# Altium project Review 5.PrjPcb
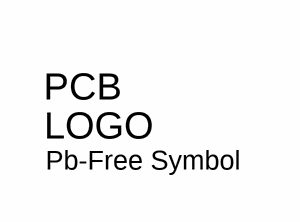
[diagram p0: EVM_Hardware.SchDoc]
CopyrightYear: 2017; PCB_Layout: Ismael Nunez; PCB_Rev: E1; PRJ_Customer: Sunon; PRJ_Engineer: Sunon Server Fan; PRJ_Number: TIDA-01619; PRJ_Title: Sunon Server Fan; SCH_Rev: E1; TechSupport: http://www.ti.com/support; TID: TIDA-01619
2 sheets, 18 parts. Net scope: flat (ports and power ports of the same name join across sheets).
Board file: Sunon PCB.PcbDoc
Sheets:
  EVM_Hardware.SchDoc
  Sunon Layout.SchDoc

## Sheet EVM_Hardware.SchDoc
size 431 x 279 mm; Date: Not shown in title block; ApprovedBy: Not shown in title block; CheckedBy: Not shown in title block; Author: Not shown in title block; CompanyName: Not shown in title block; Engineer: Not shown in title block; Organization: Not shown in title block; Address1: Not shown in title block; Address2: Not shown in title block; Address3: Not shown in title block; Address4: Not shown in title block; DocumentNumber: 1; Revision: Use project parameter SCH_Rev; SheetNumber: 3; SheetTotal: 3; PageSetup: Record=PageOptions¦CenterHorizontal=True¦CenterVertical=True¦PrintScale=1.00¦XCorrection=1.00¦YCorrection=1.00¦PrintKind=0¦BorderSize=5000000¦LeftOffset=0¦BottomOffset=0¦Orientation=2¦PaperLength=1000¦PaperWidth=1000¦Scale=100¦PaperSource=15¦PrintQuality=600¦MediaType=1¦DitherType=10¦PaperKind=Letter¦PrintScaleMode=1

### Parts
Logo2  Pb-Free Symbol  [Pb-Free_Overlay_Small]  (no BOM)

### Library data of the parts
Logo2 = CMP-0074839-1: SymbolCreator: a0412235; Library Reference: Logo

## Sheet Sunon Layout.SchDoc
size 431 x 279 mm; Date: Not shown in title block; ApprovedBy: Not shown in title block; CheckedBy: Not shown in title block; Author: Not shown in title block; CompanyName: Not shown in title block; Engineer: Not shown in title block; Organization: Not shown in title block; Address1: Not shown in title block; Address2: Not shown in title block; Address3: Not shown in title block; Address4: Not shown in title block; DocumentNumber: 1; Revision: Use project parameter SCH_Rev; SheetNumber: 2; SheetTotal: 3; PageSetup: Record=PageOptions¦CenterHorizontal=True¦CenterVertical=True¦PrintScale=1.00¦XCorrection=1.00¦YCorrection=1.00¦PrintKind=0¦BorderSize=5000000¦LeftOffset=0¦BottomOffset=0¦Orientation=2¦PaperLength=1000¦PaperWidth=1000¦Scale=100¦PaperSource=15¦PrintQuality=600¦MediaType=1¦DitherType=10¦PaperKind=Letter¦PrintScaleMode=1
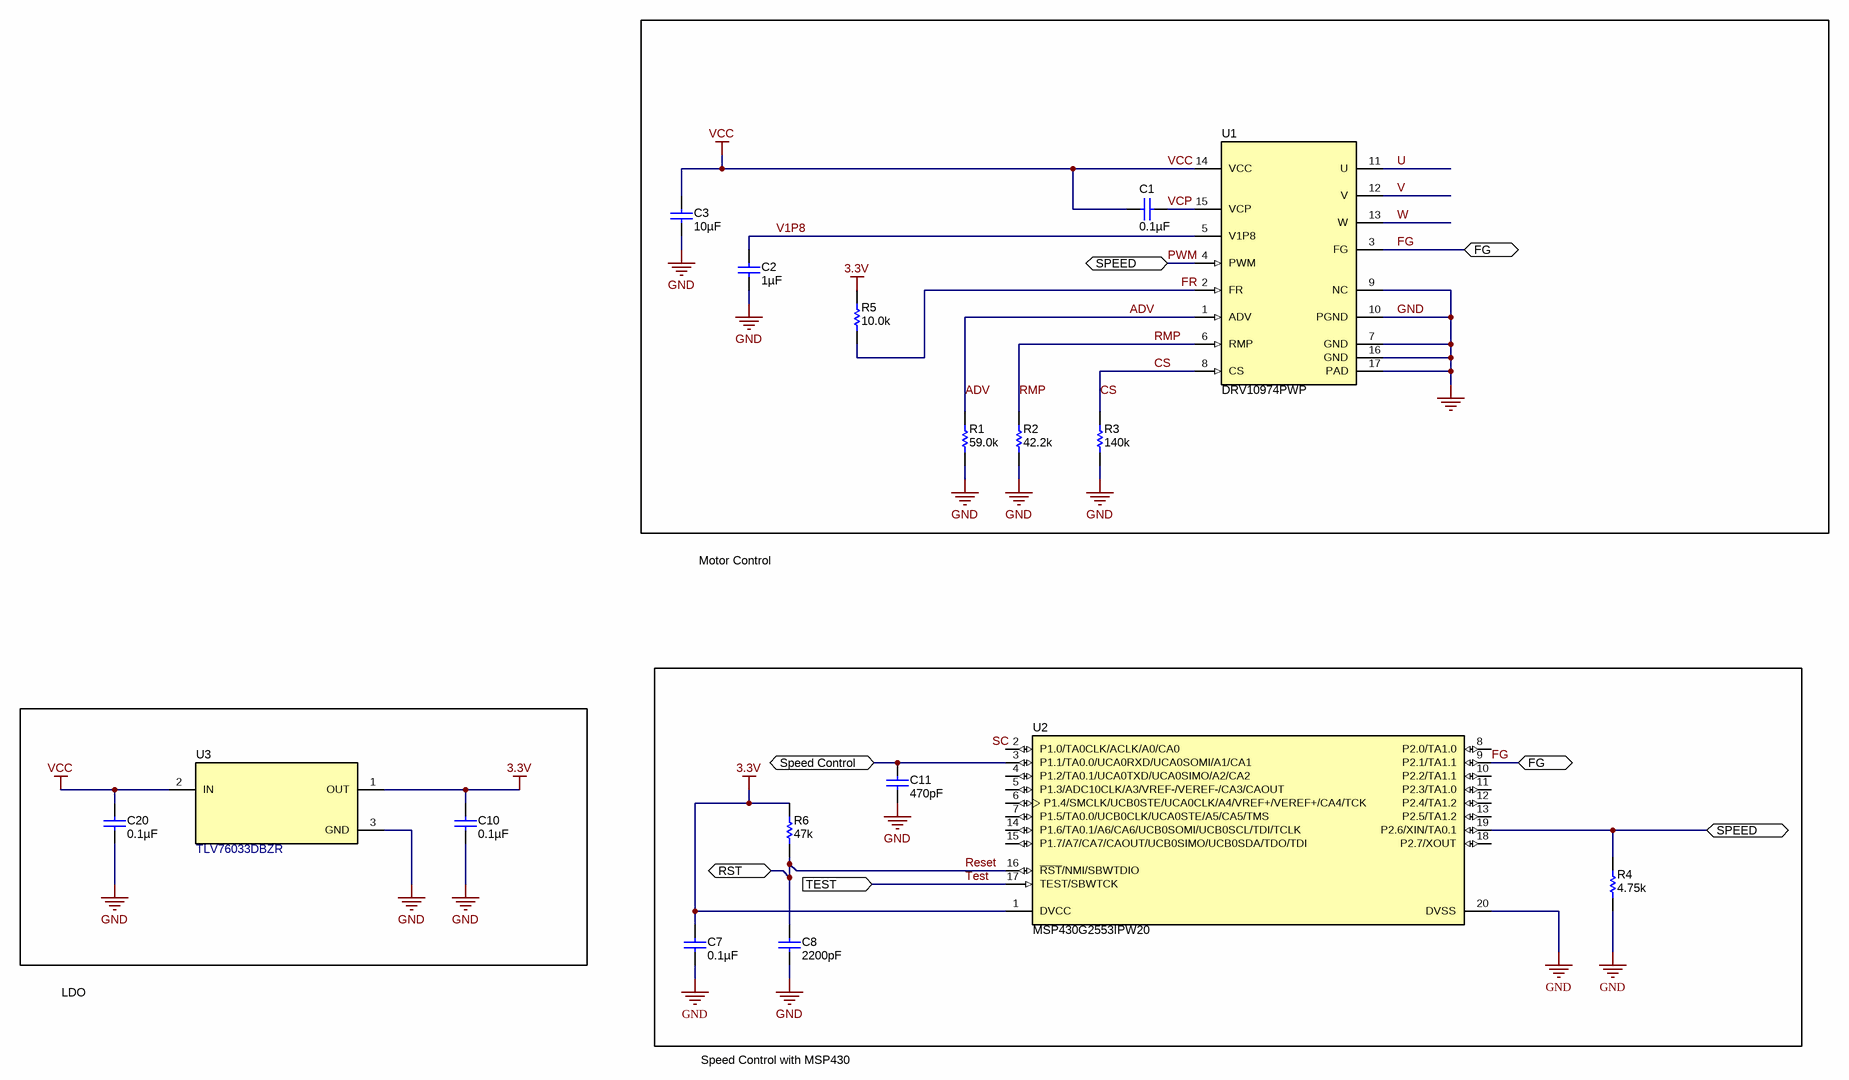
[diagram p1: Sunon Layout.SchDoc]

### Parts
C1  ValueDisplayed: 0.1µF  [0402]  (hidden comment: C1005X5R1H104K050BB)
C2  ValueDisplayed: 1µF  [0402_070]  (hidden comment: GCM155C71A105KE38D)
C3  ValueDisplayed: 10µF  [0603]  (hidden comment: GRM188R61C106MAALD)
C7  ValueDisplayed: 0.1µF  [0402]  (hidden comment: C1005X5R1H104K050BB)
C8  ValueDisplayed: 2200pF  [0402]  (hidden comment: CGA2B2X7R1H222K050BA)
C10  ValueDisplayed: 0.1µF  [0402]  (hidden comment: C1005X5R1H104K050BB)
C11  ValueDisplayed: 470pF  [0402]  (hidden comment: CGA2B2X7R1H471K050BA)
C20  ValueDisplayed: 0.1µF  [0402]  (hidden comment: C1005X5R1H104K050BB)
R1  ValueDisplayed: 59.0k  [0402]  (hidden comment: CRCW040259K0FKED)
R2  ValueDisplayed: 42.2k  [0402]  (hidden comment: CRCW040242K2FKED)
R3  ValueDisplayed: 140k  [0402]  (hidden comment: CRCW0402140KFKED)
R4  ValueDisplayed: 4.75k  [0402]  (hidden comment: CRCW04024K75FKED)
R5  ValueDisplayed: 10.0k  [0402]  (hidden comment: CRCW040210K0FKED)
R6  ValueDisplayed: 47k  [0402]  (hidden comment: CRCW040247K0JNED)
U1  DRV10974PWP  [PWP0016J_N]
U2  MSP430G2553IPW20  [PW0020A_N]
U3  TLV76033DBZR  [DBZ0003A_N]

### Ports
FG (bidir), RST (bidir), SPEED (bidir), Speed Control (bidir), TEST (in)

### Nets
3.3V: C7.1 C10.1 R5.1 R6.2 U2.1(DVCC) U3.1(OUT)
GND: C2.2 C3.2 C7.2 C8.2 C10.2 C11.2 C20.2 R1.1 R2.1 R3.1 R4.1 U1.7(GND) U1.9(NC) U1.10(PGND) U1.16(GND) U1.17(PAD) U2.20(DVSS) U3.3(GND)
VCC: C1.1 C3.1 C20.1 U1.14(VCC) U3.2(IN)
ADV: R1.2 U1.1(ADV)
CS: R3.2 U1.8(CS)
FG: U1.3(FG) U2.9(P2.1/TA1.1) ; port FG
FR: R5.2 U1.2(FR)
PWM: R4.2 U1.4(PWM) U2.19(P2.6/XIN/TA0.1) ; port SPEED
Reset: C8.1 R6.1 U2.16(~{RST}/NMI/SBWTDIO) ; port RST
RMP: R2.2 U1.6(RMP)
Speed Control: C11.1 U2.3(P1.1/TA0.0/UCA0RXD/UCA0SOMI/A1/CA1) ; port Speed Control
Test: U2.17(TEST/SBWTCK) ; port TEST
U: U1.11(U)
V: U1.12(V)
V1P8: C2.1 U1.5(V1P8)
VCP: C1.2 U1.15(VCP)
W: U1.13(W)

Not connected (* = marked no-connect by the designer): U2 2(P1.0/TA0CLK/ACLK/A0/CA0) 4(P1.2/TA0.1/UCA0TXD/UCA0SIMO/A2/CA2) 5(P1.3/ADC10CLK/A3/VREF-/VEREF-/CA3/CAOUT) 6(P1.4/SMCLK/UCB0STE/UCA0CLK/A4/VREF+/VEREF+/CA4/TCK) 7(P1.5/TA0.0/UCB0CLK/UCA0STE/A5/CA5/TMS) 8(P2.0/TA1.0) 10(P2.2/TA1.1) 11(P2.3/TA1.0) 12(P2.4/TA1.2) 13(P2.5/TA1.2) 14(P1.6/TA0.1/A6/CA6/UCB0SOMI/UCB0SCL/TDI/TCLK) 15(P1.7/A7/CA7/CAOUT/UCB0SIMO/UCB0SDA/TDO/TDI) 18(P2.7/XOUT)

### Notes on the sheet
- Motor Control
- LDO
- Speed Control with MSP430
- Labels drawn without touching a wire or pin: SC

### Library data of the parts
C1 C7 C10 C20 = C1005X5R1H104K050BB: CAP, CERM, 0.1 µF, 50 V,+/- 10%, X5R, 0402; Manufacturer: TDK; Polarized: N; CompType: Capacitor; Value: 0.1uF; U/M: EA; Cap_F: 0.0000001; Tolerance_%: 10; ESR_ohm: 0.039064; Value1: 0.039064 ohm; VDC_V: 50; Value2: 50V; IRMS_A: 0.814669; TaMin_C: -55; TaMax_C: 85; SizeArea_mm2: 0.5; SizeAreaWB_mm2: 3; SizeX_mm: 1; SizeZ_mm: 0.6; AEC Category: Q200; Green_Lifecycle: NRND; Green_REACh: Passed
C2 = GCM155C71A105KE38D: CAP, CERM, 1 µF, 10 V,+/- 10%, X7S, AEC-Q200 Grade 1, 0402; Manufacturer: MuRata; Polarized: N; CompType: Capacitor; Value: 1uF; U/M: EA; Cap_F: 0.000001; Tolerance_%: 10; Value2: 10V; TaMin_C: -55; TaMax_C: 125; Cap_Case: 0402; SizeArea_mm2: 0.5; SizeAreaWB_mm2: 3; SizeX_mm: 1; SizeZ_mm: 0.7; AEC Category: Q200; AEC Qualified: Y
C3 = GRM188R61C106MAALD: CAP, CERM, 10 µF, 16 V,+/- 20%, X5R, 0603; Manufacturer: MuRata; Polarized: N; CompType: Capacitor; Value: 10uF; U/M: EA; Cap_F: 0.00001; Tolerance_%: 20; VDC_V: 16; Value2: 16V; TaMin_C: -55; TaMax_C: 85; SizeArea_mm2: 1.28; SizeAreaWB_mm2: 4.68; SizeX_mm: 1.6; SizeY_mm: 0.8; SizeZ_mm: 1; AEC Category: Q200; Green_Lifecycle: Active; Green_REACh: Passed
C8 = CGA2B2X7R1H222K050BA: CAP, CERM, 2200 pF, 50 V,+/- 10%, X7R, AEC-Q200 Grade 1, 0402; Manufacturer: TDK; Polarized: N; CompType: Capacitor; Value: 2200pF; U/M: EA; Cap_F: 0.0000000022; Tolerance_%: 10; ESR_ohm: 1.07794; Value1: 1.07794 ohm; VDC_V: 50; Value2: 50V; IRMS_A: 0.264071; TaMin_C: -55; TaMax_C: 125; SizeArea_mm2: 0.5; SizeAreaWB_mm2: 3; SizeX_mm: 1; SizeZ_mm: 0.6; AEC Category: Q200; AEC Qualified: Y
C11 = CGA2B2X7R1H471K050BA: CAP, CERM, 470 pF, 50 V,+/- 10%, X7R, AEC-Q200 Grade 1, 0402; Manufacturer: TDK; Polarized: N; CompType: Capacitor; Value: 470pF; U/M: EA; Cap_F: 0.00000000047; Tolerance_%: 10; ESR_ohm: 4.96489; Value1: 4.96489 ohm; VDC_V: 50; Value2: 50V; IRMS_A: 0.228414; TaMin_C: -55; TaMax_C: 125; SizeArea_mm2: 0.5; SizeAreaWB_mm2: 3; SizeX_mm: 1; SizeZ_mm: 0.6; AEC Category: Q200; AEC Qualified: Y
R1 = CRCW040259K0FKED: RES, 59.0 k, 1%, 0.063 W, 0402; Manufacturer: Vishay-Dale; CompType: Resistor; Value: 59.0k; Res_ohm: 59000; Value_Code: 59k0; Tolerance_%: 1; Power_W: 0.063; Value2: 0.063W; VDC_V: 50; TempCo: 100 ppm/C; SizeArea_mm2: 0.5; SizeZ_mm: 0.6; EIA_Code: E96; U/M: EA; AEC Category: Q200
R2 = CRCW040242K2FKED: RES, 42.2 k, 1%, 0.063 W, 0402; Manufacturer: Vishay-Dale; CompType: Resistor; Value: 42.2k; Res_ohm: 42200; Value_Code: 42k2; Tolerance_%: 1; Power_W: 0.063; Value2: 0.063W; VDC_V: 50; TempCo: 100 ppm/C; SizeArea_mm2: 0.5; SizeZ_mm: 0.6; EIA_Code: E96; U/M: EA; AEC Category: Q200
R3 = CRCW0402140KFKED: RES, 140 k, 1%, 0.063 W, 0402; Manufacturer: Vishay-Dale; CompType: Resistor; Value: 140k; Res_ohm: 140000; Tolerance_%: 1; Power_W: 0.063; Value2: 0.063W; VDC_V: 50; TempCo: 100 ppm/C; SizeArea_mm2: 0.5; SizeZ_mm: 0.6; EIA_Code: E96; U/M: EA; AEC Category: Q200; Green_Lifecycle: Active; Green_REACh: Passed
R4 = CRCW04024K75FKED: RES, 4.75 k, 1%, 0.063 W, 0402; Manufacturer: Vishay-Dale; CompType: Resistor; Value: 4.75k; Res_ohm: 4750; Value_Code: 4k75; Tolerance_%: 1; Power_W: 0.063; Value2: 0.063W; VDC_V: 50; TempCo: 100 ppm/C; SizeArea_mm2: 0.5; SizeZ_mm: 0.6; EIA_Code: E96; U/M: EA; AEC Category: Q200; Green_Lifecycle: Active; Green_REACh: Passed
R5 = CRCW040210K0FKED: RES, 10.0 k, 1%, 0.063 W, 0402; Manufacturer: Vishay-Dale; CompType: Resistor; Value: 10.0k; Res_ohm: 10000; Value_Code: 10k0; Tolerance_%: 1; Power_W: 0.063; Value2: 0.063W; VDC_V: 50; TempCo: 100 ppm/C; SizeArea_mm2: 0.5; SizeZ_mm: 0.6; EIA_Code: E96; U/M: EA; AEC Category: Q200; Green_Lifecycle: Active; Green_REACh: Passed
R6 = CRCW040247K0JNED: RES, 47 k, 5%, 0.063 W, 0402; Manufacturer: Vishay-Dale; CompType: Resistor; Value: 47k; Res_ohm: 47000; Value_Code: 47k0; Tolerance_%: 5; Power_W: 0.063; Value2: 0.063W; VDC_V: 50; TempCo: 200 ppm/C; SizeArea_mm2: 0.5; SizeX_mm: 1; SizeZ_mm: 0.6; EIA_Code: E24; U/M: EA; AEC Category: Q200; Green_Lifecycle: Active; Green_REACh: Passed
U1 = CMP-0065208-6: 12-V, Three-Phase, Sensorless BLDC Motor Driver, PWP0016J (TSSOP-16); Manufacturer: Texas Instruments; SizeX_mm: 6.4; SizeY_mm: 5.0; CompType: IC; SizeZ_mm: 1.2; SizeArea_mm2: 32.0; SizeAreaWB_mm2: 58.8; U/M: EA
U2 = MSP430G2553IPW20: 16 MHz Mixed Signal Microcontroller with 16 KB Flash, 512 B SRAM and 24 GPIOs, -40 to 85 degC, 20-pin SOP (PW), Green (RoHS & no Sb/Br); Alternate Manufacturer: Texas Instruments; Alternate PartNumber: Equivalent; ADC: 10-bit SAR; ADC Channels: 8; Brown Out Reset: Yes; Flash(KB): 16; GPIO: 24; Pin/Package: 0DIESALE, 0WAFERSALE, 20PDIP, 20TSSOP, 28TSSOP, 32QFN; SRAM(B): 512; SubFamily: Value Line; Timers - 16-bit: 2; USCI_A (UART/LIN/IrDA/SPI): 1
U3 = CMP-0074893-1: 100-mA, 30-V, Fixed-Output, Linear-Voltage Regulator, DBZ0003A (SOT-23-3); Alternate PartNumber: TLV76033DBZT; Alternate Manufacturer: Texas Instruments; SizeAreaWB_mm2: 14.0; SizeZ_mm: 1.12; SizeX_mm: 2.5; SizeY_mm: 3.0; SizeArea_mm2: 7.5; CompType: IC; AEC Qualified: N; AEC Category: Q200

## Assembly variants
001: not fitted C7 C8 C10 C11 C20 R4 R5 R6 U2 U3
Do Not Populate: not fitted C7 C8 C10 C11 C20 R4 R5 R6 U2 U3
